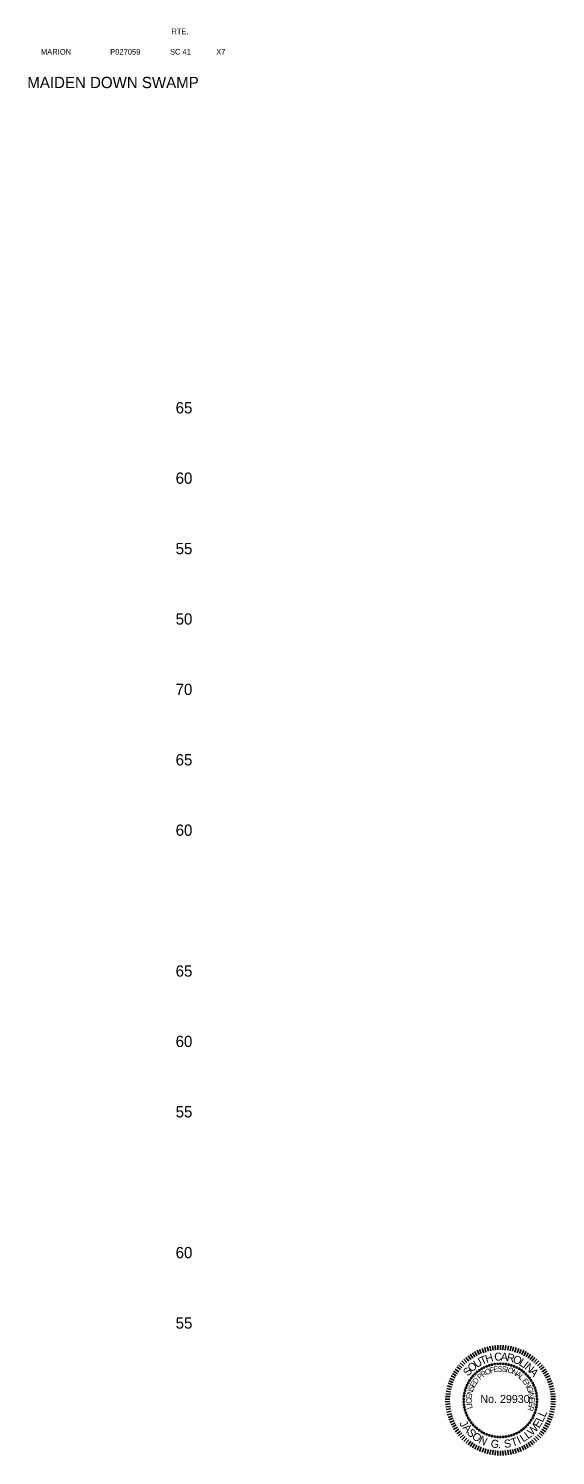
# Model space of a CAD drawing. Extents: x 1001 to 1184, y 1001 to 1447.
# Drawn here: x 1146.5 to 1183.9, y 1116 to 1217.3 of the extents above; entities that cross this region are included whole.
import ezdxf

# ---------------------------------------------------------------- set-up
doc = ezdxf.new("R2010")
doc.units = 0
for name, color, linetype in [('RD_HC_Cl', 7, 'Continuous'), ('RD_SHT_TX', 7, 'Continuous'), ('RD_TX_PEShield', 7, 'Continuous'), ('RD_XS_TX_Elev_EX', 7, 'Continuous')]:
    doc.layers.add(name, color=color, linetype=linetype)

# ---------------------------------------------------------------- blocks, each defined once
blk = doc.blocks.new('STILLWELL')
at = {"layer": 'RD_TX_PEShield'}
for p, q in [((-21.1, 28.1), (-23, 30.7)), ((-19.7, 29.1), (-21.5, 31.8)), ((-18.2, 30), (-19.9, 32.8)), ((-16.7, 30.8), (-18.2, 33.7)), ((-15.1, 31.6), (-16.5, 34.6)), ((-13.6, 32.3), (-14.8, 35.3)), ((-11.9, 32.9), (-13, 36)), ((-10.3, 33.4), (-11.2, 36.6)), ((-8.6, 33.9), (-9.4, 37.1)), ((-6.9, 34.3), (-7.5, 37.5)), ((-5.2, 34.6), (-5.7, 37.8)), ((-3.5, 34.8), (-3.8, 38)), ((-1.8, 34.9), (-1.9, 38.2)), ((0, 34.9), (0, 38.2)), ((1.7, 34.9), (1.9, 38.2)), ((3.4, 34.8), (3.7, 38)), ((5.2, 34.6), (5.6, 37.8)), ((6.9, 34.3), (7.5, 37.5)), ((8.6, 33.9), (9.3, 37.1)), ((10.2, 33.4), (11.2, 36.6)), ((11.9, 32.9), (13, 36)), ((13.5, 32.3), (14.7, 35.3)), ((15.1, 31.6), (16.5, 34.6)), ((16.6, 30.8), (18.2, 33.7)), ((18.2, 30), (19.8, 32.8)), ((19.6, 29.1), (21.4, 31.8)), ((21.1, 28.1), (23, 30.7)), ((-29.5, 19.4), (-32.2, 21.3)), ((-28.5, 20.9), (-31.1, 22.8)), ((-27.4, 22.2), (-29.9, 24.3)), ((-26.3, 23.5), (-28.7, 25.7)), ((-25.1, 24.7), (-27.4, 27.1)), ((-23.8, 25.9), (-26, 28.4)), ((-22.5, 27), (-24.5, 29.6)), ((22.4, 27), (24.5, 29.6)), ((23.8, 25.9), (25.9, 28.4)), ((25, 24.7), (27.3, 27.1)), ((26.2, 23.5), (28.6, 25.7)), ((27.4, 22.2), (29.9, 24.3)), ((28.5, 20.9), (31.1, 22.8)), ((29.5, 19.4), (32.2, 21.3)), ((-34.1, 10.2), (-37.2, 11.2)), ((-33.6, 11.8), (-36.6, 12.9)), ((-32.9, 13.4), (-35.9, 14.7)), ((-32.2, 15), (-35.1, 16.4)), ((-31.4, 16.5), (-34.2, 18.1)), ((-30.5, 18), (-33.3, 19.7)), ((30.4, 18), (33.2, 19.7)), ((31.3, 16.5), (34.2, 18.1)), ((32.1, 15), (35.1, 16.4)), ((32.9, 13.4), (35.9, 14.7)), ((33.5, 11.8), (36.6, 12.9)), ((34.1, 10.2), (37.2, 11.2)), ((-35.9, -0.1), (-39.2, 0)), ((-35.8, 1.7), (-39.1, 1.9)), ((-35.6, 3.4), (-38.9, 3.8)), ((-35.4, 5.1), (-38.6, 5.7)), ((-35.1, 6.8), (-38.2, 7.5)), ((-34.6, 8.5), (-37.8, 9.4)), ((34.6, 8.5), (37.7, 9.4)), ((35, 6.8), (38.2, 7.5)), ((35.3, 5.1), (38.5, 5.7)), ((35.6, 3.4), (38.8, 3.8)), ((35.7, 1.7), (39, 1.9)), ((35.8, -0.1), (39.1, 0)), ((-35.9, -1.8), (-39.2, -1.9)), ((-35.8, -3.5), (-39.1, -3.8)), ((-35.6, -5.3), (-38.9, -5.6)), ((-35.4, -7), (-38.6, -7.5)), ((-35.1, -8.7), (-38.2, -9.4)), ((35, -8.7), (38.2, -9.4)), ((35.3, -7), (38.5, -7.5)), ((35.6, -5.3), (38.8, -5.6)), ((35.7, -3.5), (39, -3.8)), ((35.8, -1.8), (39.1, -1.9)), ((-34.6, -10.4), (-37.8, -11.2)), ((-34.1, -12), (-37.2, -13)), ((-33.6, -13.6), (-36.6, -14.8)), ((-32.9, -15.3), (-35.9, -16.6)), ((-32.2, -16.8), (-35.1, -18.3)), ((-31.4, -18.4), (-34.2, -19.9)), ((-30.5, -19.9), (-33.3, -21.6)), ((30.4, -19.9), (33.2, -21.6)), ((31.3, -18.4), (34.2, -19.9)), ((32.1, -16.8), (35.1, -18.3)), ((32.9, -15.3), (35.9, -16.6)), ((33.5, -13.6), (36.6, -14.8)), ((34.1, -12), (37.2, -13)), ((34.6, -10.4), (37.7, -11.2)), ((-29.5, -21.3), (-32.2, -23.2)), ((-28.5, -22.7), (-31.1, -24.7)), ((-27.4, -24.1), (-29.9, -26.2)), ((-26.3, -25.4), (-28.7, -27.6)), ((-25.1, -26.6), (-27.4, -28.9)), ((-23.8, -27.8), (-26, -30.2)), ((-22.5, -28.9), (-24.5, -31.4)), ((-21.1, -29.9), (-23, -32.6)), ((21.1, -29.9), (23, -32.6)), ((22.4, -28.9), (24.5, -31.4)), ((23.8, -27.8), (25.9, -30.2)), ((25, -26.6), (27.3, -28.9)), ((26.2, -25.4), (28.6, -27.6)), ((27.4, -24.1), (29.9, -26.2)), ((28.5, -22.7), (31.1, -24.7)), ((29.5, -21.3), (32.2, -23.2)), ((-19.7, -30.9), (-21.5, -33.7)), ((-18.2, -31.8), (-19.9, -34.7)), ((-16.7, -32.7), (-18.2, -35.6)), ((-15.1, -33.5), (-16.5, -36.4)), ((-13.6, -34.1), (-14.8, -37.2)), ((-11.9, -34.8), (-13, -37.8)), ((-10.3, -35.3), (-11.2, -38.4)), ((-8.6, -35.8), (-9.4, -38.9)), ((-6.9, -36.1), (-7.5, -39.3)), ((-5.2, -36.4), (-5.7, -39.7)), ((-3.5, -36.6), (-3.8, -39.9)), ((-1.8, -36.8), (-1.9, -40)), ((0, -36.8), (0, -40.1)), ((1.7, -36.8), (1.9, -40)), ((3.4, -36.6), (3.7, -39.9)), ((5.2, -36.4), (5.6, -39.7)), ((6.9, -36.1), (7.5, -39.3)), ((8.6, -35.8), (9.3, -38.9)), ((10.2, -35.3), (11.2, -38.4)), ((11.9, -34.8), (13, -37.8)), ((13.5, -34.1), (14.7, -37.2)), ((15.1, -33.5), (16.5, -36.4)), ((16.6, -32.7), (18.2, -35.6)), ((18.2, -31.8), (19.8, -34.7)), ((19.6, -30.9), (21.4, -33.7))]:
    blk.add_line(p, q, dxfattribs=at)
for centre in [(-15, 20.4), (-13.3, 21.5), (-11.6, 22.4), (-9.8, 23.2), (-7.9, 23.9), (-6, 24.4), (-4, 24.8), (-2, 25), (0, 25.1), (2, 25), (3.9, 24.8), (5.9, 24.4), (7.8, 23.9), (9.7, 23.2), (11.5, 22.4), (13.3, 21.5), (15, 20.4), (-23.8, 9.7), (-22.9, 11.5), (-21.9, 13.2), (-20.7, 14.9), (-19.5, 16.4), (-18.1, 17.8), (-16.6, 19.2), (16.5, 19.2), (18, 17.8), (19.4, 16.4), (20.7, 14.9), (21.8, 13.2), (22.9, 11.5), (23.7, 9.7), (-26.1, 0.1), (-25.9, 2.1), (-25.6, 4), (-25.1, 6), (-24.5, 7.9), (24.5, 7.9), (25.1, 6), (25.5, 4), (25.8, 2.1), (26, 0.1), (-26.1, -1.9), (-25.9, -3.9), (-25.6, -5.9), (-25.1, -7.8), (-24.5, -9.7), (24.5, -9.7), (25.1, -7.8), (25.5, -5.9), (25.8, -3.9), (26, -1.9), (-23.8, -11.6), (-22.9, -13.4), (-21.9, -15.1), (-20.7, -16.7), (-19.5, -18.3), (-18.1, -19.7), (18, -19.7), (19.4, -18.3), (20.7, -16.7), (21.8, -15.1), (22.9, -13.4), (23.7, -11.6), (-16.6, -21), (-15, -22.2), (-13.3, -23.3), (-11.6, -24.3), (-9.8, -25.1), (-7.9, -25.8), (-6, -26.3), (-4, -26.7), (-2, -26.9), (0, -27), (2, -26.9), (3.9, -26.7), (5.9, -26.3), (7.8, -25.8), (9.7, -25.1), (11.5, -24.3), (13.3, -23.3), (15, -22.2), (16.5, -21)]:
    blk.add_circle(centre, 0.49, dxfattribs=at)
for s, height, rotation, p in [('T', 5.68, 23.5044, (-13.2, 24.1)), ('H', 5.68, 16.1357, (-9.9, 25.6)), ('C', 5.68, 4.076, (-4.2, 27.1)), ('A', 5.68, 355.3651, (0.1, 27.4)), ('R', 5.68, 347.3188, (4.1, 27.1)), ('O', 5.68, 338.6079, (8.3, 26.2)), ('S', 5.68, 49.6435, (-22.9, 15.8)), ('O', 5.68, 41.5972, (-20.4, 18.8)), ('U', 5.68, 32.2152, (-16.9, 21.8)), ('O', 3.92, 24.9735, (-10, 16.9)), ('F', 3.92, 15.9995, (-7.1, 18.3)), ('E', 3.92, 8.9511, (-4.7, 19)), ('S', 3.92, 1.2546, (-1.9, 19.4)), ('S', 3.92, 353.558, (0.8, 19.5)), ('I', 3.92, 345.8615, (3.5, 19.2)), ('O', 3.92, 342.6583, (4.7, 19)), ('N', 3.92, 333.6842, (7.7, 18)), ('L', 5.68, 329.226, (12.6, 24.4)), ('I', 5.68, 322.5218, (15.5, 22.8)), ('N', 5.68, 319.1729, (16.8, 21.8)), ('A', 5.68, 310.4621, (20.1, 19)), ('E', 3.92, 60.2341, (-18.5, 7.9)), ('D', 3.92, 52.5376, (-17.1, 10.3)), ('P', 3.92, 41.0022, (-14.5, 13.5)), ('R', 3.92, 33.3057, (-12.5, 15.3)), ('A', 3.92, 325.3521, (10.4, 16.7)), ('L', 3.92, 317.6555, (12.6, 15.1)), ('E', 3.92, 308.0396, (15.1, 12.8)), ('N', 3.92, 300.343, (16.8, 10.6)), ('C', 3.92, 92.2915, (-20.4, -3.2)), ('E', 3.92, 83.9594, (-20.5, -0.2)), ('N', 3.92, 76.2628, (-20.2, 2.5)), ('S', 3.92, 67.9307, (-19.5, 5.4)), ('G', 3.92, 292.0109, (18.3, 8.1)), ('I', 3.92, 283.0368, (19.5, 5.1)), ('N', 3.92, 279.8336, (19.8, 4)), ('E', 3.92, 271.5014, (20.3, 1.1)), ('I', 3.92, 95.4947, (-20.2, -4.3)), ('L', 3.92, 101.9075, (-19.7, -6.6)), ('R', 3.92, 256.1083, (20.1, -4.4)), ('E', 3.92, 263.8049, (20.4, -1.7)), ('L', 5.68, 65.098, (31.6, -13.3)), ('J', 5.68, 299.033, (-29.4, -17.3)), ('A', 5.68, 310.5887, (-27.2, -20.6)), ('W', 5.68, 47.0518, (22.6, -26.4)), ('E', 5.68, 56.4327, (27.3, -21.1)), ('L', 5.68, 65.098, (30, -16.9)), ('S', 5.68, 310.5887, (-24.3, -24)), ('O', 5.68, 321.0072, (-20.8, -27.4)), ('N', 5.68, 333.4326, (-16, -30.8)), ('G', 5.68, 352.2045, (-7.2, -34.2)), ('S', 5.68, 8.0826, (2.9, -34.8)), ('T', 5.68, 18.9019, (8.5, -33.9)), ('I', 5.68, 25.3991, (13.3, -32.2)), ('L', 5.68, 34.0644, (16.2, -30.9)), ('L', 5.68, 37.6708, (19.6, -28.7)), ('.', 5.68, 0.8698, (-1.8, -34.9))]:
    blk.add_text(s, height=height, rotation=rotation, dxfattribs=at).set_placement(p)
blk.add_text('No. 29930', height=5.68, dxfattribs=at).set_placement((-14.3, -2.8))

msp = doc.modelspace()

# ---------------------------------------------------------------- block references
at = {"layer": 'RD_HC_Cl', "xscale": 0.1, "yscale": 0.10000000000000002}
msp.add_blockref('STILLWELL', (1180, 1120), dxfattribs=at)

# ---------------------------------------------------------------- texts
at = {"layer": 'RD_SHT_TX'}
for s, height, p in [('RTE.', 0.4, (1156.62, 1216.93)), ('MARION', 0.4, (1147.35, 1215.48)), ('P027059', 0.4, (1152.27, 1215.48)), ('SC 41', 0.4, (1156.52, 1215.48)), ('X7', 0.4, (1159.8, 1215.48)), ('MAIDEN DOWN SWAMP', 0.8, (1146.38, 1213.1))]:
    msp.add_text(s, height=height, dxfattribs=at).set_placement(p)
at = {"layer": 'RD_XS_TX_Elev_EX'}
for s, p in [('65', (1156.92, 1190)), ('60', (1156.92, 1185)), ('55', (1156.92, 1180)), ('50', (1156.92, 1175)), ('70', (1156.92, 1170)), ('65', (1156.92, 1165)), ('60', (1156.92, 1160)), ('65', (1156.92, 1150)), ('60', (1156.92, 1145)), ('55', (1156.92, 1140)), ('60', (1156.92, 1130)), ('55', (1156.92, 1125))]:
    msp.add_text(s, height=0.8, dxfattribs=at).set_placement(p)

doc.saveas('drawing.dxf')
